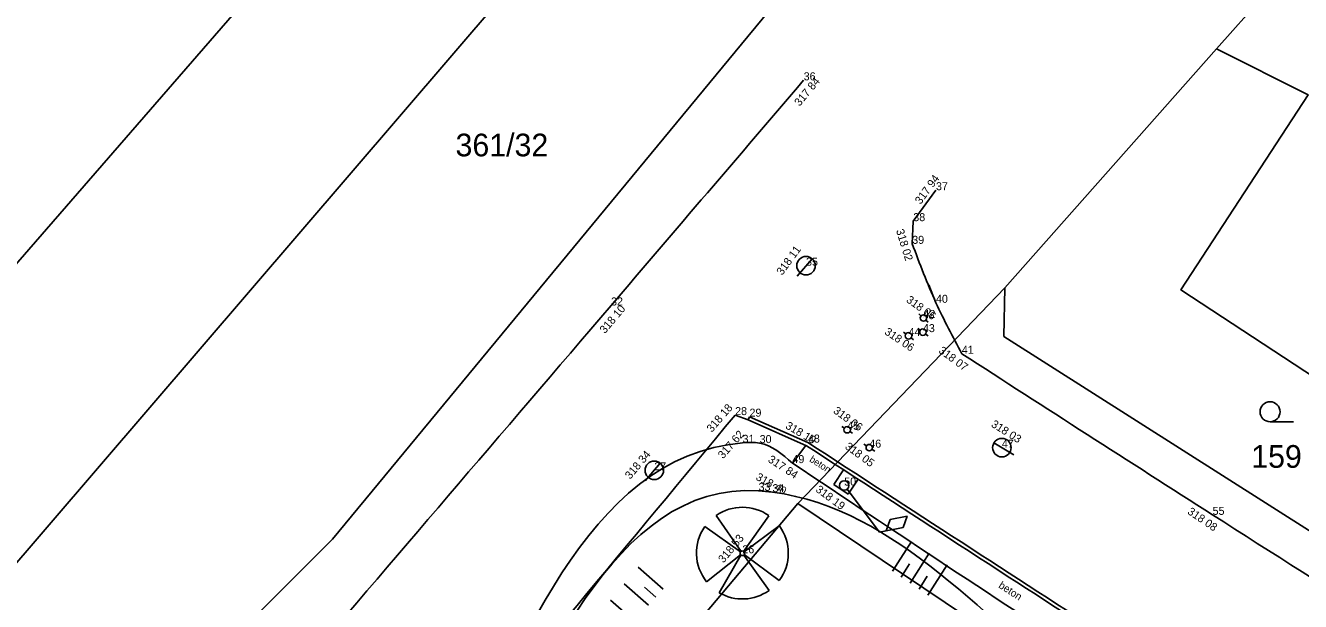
# Model space of a CAD drawing. Extents: x -742884 to -742543, y -1054677 to -1054433.
# Drawn here: x -742753.9 to -742706.11, y -1054488.13 to -1054466.53 of the extents above; entities that cross this region are included whole.
import ezdxf

# ---------------------------------------------------------------- set-up
doc = ezdxf.new("R2010")
doc.units = 0
for name, color, linetype in [('Vrstva 1', 7, 'Continuous'), ('Vrstva 10', 7, 'Continuous'), ('Vrstva 11', 7, 'Continuous'), ('Vrstva 12', 7, 'Continuous'), ('Vrstva 13', 7, 'Continuous'), ('Vrstva 15', 7, 'Continuous'), ('Vrstva 2', 7, 'Continuous'), ('Vrstva 3', 7, 'Continuous'), ('Vrstva 4', 7, 'Continuous'), ('Vrstva 50', 7, 'Continuous'), ('Vrstva 7', 7, 'Continuous'), ('Vrstva 8', 7, 'Continuous'), ('Vrstva 9', 7, 'Continuous')]:
    doc.layers.add(name, color=color, linetype=linetype)

# ---------------------------------------------------------------- blocks, each defined once
blk = doc.blocks.new('Z15')
at = {"layer": 'Vrstva 2'}
for p, q in [((-10, 2), (-8, 6)), ((-10, -2), (-10, 2)), ((-8, 6), (-6, 8)), ((-6, 8), (-2, 10)), ((-2, 10), (2, 10)), ((2, 10), (6, 8)), ((6, 8), (8, 6)), ((8, 6), (10, 2)), ((10, 2), (10, -2)), ((-8, -6), (-10, -2)), ((-6, -8), (-8, -6)), ((-2, -10), (-6, -8)), ((2, -10), (-2, -10)), ((6, -8), (2, -10)), ((8, -6), (6, -8)), ((10, -2), (8, -6))]:
    blk.add_line(p, q, dxfattribs=at)

msp = doc.modelspace()

# ---------------------------------------------------------------- linework, layer by layer
at = {"layer": 'Vrstva 1'}
for p, q in [((-742724.73, -1054468.59), (-742724.73, -1054468.59)), ((-742719.77, -1054472.71), (-742719.77, -1054472.71)), ((-742720.62, -1054473.87), (-742720.62, -1054473.87)), ((-742720.66, -1054474.72), (-742720.66, -1054474.72)), ((-742724.64, -1054475.54), (-742724.64, -1054475.54)), ((-742731.95, -1054477.03), (-742731.95, -1054477.03)), ((-742719.77, -1054476.93), (-742719.77, -1054476.93)), ((-742720.24, -1054477.5), (-742720.24, -1054477.5)), ((-742720.8, -1054478.17), (-742720.8, -1054478.17)), ((-742720.26, -1054478.03), (-742720.26, -1054478.03)), ((-742718.8, -1054478.84), (-742718.8, -1054478.84)), ((-742727.3, -1054481.14), (-742727.3, -1054481.14)), ((-742726.76, -1054481.2), (-742726.76, -1054481.2)), ((-742723.1, -1054481.69), (-742723.1, -1054481.69)), ((-742727.02, -1054482.18), (-742727.02, -1054482.18)), ((-742726.38, -1054482.19), (-742726.38, -1054482.19)), ((-742724.57, -1054482.17), (-742724.57, -1054482.17)), ((-742722.27, -1054482.36), (-742722.27, -1054482.36)), ((-742717.3, -1054482.36), (-742717.3, -1054482.36)), ((-742730.33, -1054483.21), (-742730.33, -1054483.21)), ((-742725.15, -1054482.94), (-742725.15, -1054482.94)), ((-742726.42, -1054483.98), (-742726.42, -1054483.98)), ((-742725.9, -1054484.03), (-742725.9, -1054484.03)), ((-742723.21, -1054483.78), (-742723.21, -1054483.78)), ((-742709.4, -1054484.88), (-742709.4, -1054484.88)), ((-742727.03, -1054486.32), (-742727.03, -1054486.32))]:
    msp.add_line(p, q, dxfattribs=at)
at = {"layer": 'Vrstva 10'}
for p, q in [((-742727.07, -1054486.251), (-742728.008, -1054484.9)), ((-742726.981, -1054486.251), (-742726.03, -1054484.913)), ((-742727.095, -1054486.261), (-742728.434, -1054485.319)), ((-742726.966, -1054486.271), (-742725.644, -1054485.293)), ((-742727.1, -1054486.379), (-742728.368, -1054487.397)), ((-742727.082, -1054486.395), (-742727.897, -1054487.803)), ((-742726.972, -1054486.39), (-742726.028, -1054487.718)), ((-742726.958, -1054486.37), (-742725.644, -1054487.339))]:
    msp.add_line(p, q, dxfattribs=at)
for centre, radius, start, end in [((-742727.026, -1054486.314), 1.72, 54.7465, 124.8105), ((-742727.028, -1054486.31), 1.721, 144.8767, 218.9336), ((-742727.026, -1054486.314), 1.72, 323.4756, 36.2971), ((-742727.026, -1054486.314), 1.72, 239.6151, 305.4552)]:
    msp.add_arc(centre, radius, start, end, dxfattribs=at)
at = {"layer": 'Vrstva 11'}
for p, q in [((-742720.691, -1054485.874), (-742721.401, -1054486.992)), ((-742720.737, -1054487.439), (-742720.025, -1054486.313)), ((-742729.998, -1054487.666), (-742730.939, -1054486.844)), ((-742720.763, -1054486.722), (-742721.073, -1054487.213)), ((-742720.069, -1054487.89), (-742719.349, -1054486.758)), ((-742730.544, -1054488.26), (-742731.459, -1054487.465)), ((-742720.403, -1054487.664), (-742720.095, -1054487.179)), ((-742730.272, -1054487.963), (-742730.698, -1054487.591)), ((-742731.972, -1054488.075), (-742731.082, -1054488.852))]:
    msp.add_line(p, q, dxfattribs=at)
for points in [[(-742777.63, -1054542.12), (-742764.61, -1054526.83), (-742751.7, -1054511.56), (-742738.47, -1054495.82), (-742727.02, -1054482.18), (-742726.38, -1054482.19), (-742725.15, -1054482.94)], [(-742776.7, -1054542.68), (-742764.01, -1054527.79), (-742751.11, -1054512.75), (-742737.61, -1054496.47), (-742726.42, -1054483.98), (-742725.9, -1054484.03), (-742714, -1054491.86), (-742704.819, -1054497.481), (-742700.94, -1054500.269), (-742696.44, -1054503.39), (-742688.83, -1054509.5), (-742682.54, -1054514.17), (-742675.15, -1054519.77), (-742673.01, -1054522.11), (-742671.05, -1054524.7)]]:
    msp.add_spline(points, degree=3, dxfattribs=at)
at = {"layer": 'Vrstva 12'}
for p, q in [((-742723.234, -1054483.19), (-742723.601, -1054483.741)), ((-742723.601, -1054483.741), (-742723.059, -1054484.1)), ((-742722.688, -1054483.544), (-742723.059, -1054484.1))]:
    msp.add_line(p, q, dxfattribs=at)
for points in [[(-742723.103, -1054483.923), (-742721.882, -1054485.535)], [(-742721.633, -1054485.482), (-742721.483, -1054485.059)], [(-742721.483, -1054485.059), (-742720.849, -1054484.926)], [(-742721, -1054485.351), (-742720.849, -1054484.926)], [(-742721.882, -1054485.535), (-742721, -1054485.351)]]:
    msp.add_lwpolyline(points, dxfattribs=at)
msp.add_circle((-742723.212, -1054483.779), 0.18, dxfattribs=at)
at = {"layer": 'Vrstva 13'}
msp.add_line((-742724.65, -1054482.277), (-742725.15, -1054482.94), dxfattribs=at)
msp.add_spline([(-742725.15, -1054482.94), (-742713.48, -1054490.62), (-742699.44, -1054499.41), (-742696.97, -1054500.991)], degree=3, dxfattribs=at)
at = {"layer": 'Vrstva 4'}
for p, q in [((-742719.77, -1054472.71), (-742720.62, -1054473.87)), ((-742720.62, -1054473.87), (-742720.66, -1054474.72)), ((-742720.039, -1054476.262), (-742719.77, -1054476.93)), ((-742727.3, -1054481.14), (-742726.813, -1054481.319)), ((-742726.813, -1054481.319), (-742726.76, -1054481.2)), ((-742726.813, -1054481.319), (-742724.623, -1054482.289)), ((-742724.57, -1054482.17), (-742726.76, -1054481.2))]:
    msp.add_line(p, q, dxfattribs=at)
for points in [[(-742783.23, -1054536.93), (-742770.7, -1054522.44), (-742757.28, -1054506.67), (-742744.15, -1054491.3), (-742731.95, -1054477.03), (-742724.73, -1054468.59)], [(-742720.66, -1054474.72), (-742719.77, -1054476.93), (-742718.8, -1054478.84)], [(-742718.8, -1054478.84), (-742709.4, -1054484.88), (-742695.99, -1054493.43), (-742680.4, -1054503.55), (-742661.01, -1054516), (-742635.78, -1054532.31)], [(-742778.49, -1054541.37), (-742765.63, -1054526.43), (-742752.39, -1054510.77), (-742739.19, -1054495.37), (-742727.3, -1054481.14)], [(-742668.427, -1054518.574), (-742683.74, -1054508.68), (-742696.59, -1054500.4), (-742699.13, -1054498.77), (-742713.15, -1054489.73), (-742724.623, -1054482.289)], [(-742668.31, -1054518.5), (-742683.67, -1054508.57), (-742699.06, -1054498.66), (-742713.08, -1054489.62), (-742724.57, -1054482.17)]]:
    msp.add_spline(points, degree=3, dxfattribs=at)
at = {"layer": 'Vrstva 50'}
for p, q in [((-742780.33, -1054517.08), (-742715.033, -1054440.982)), ((-742700.42, -1054457.44), (-742709.25, -1054467.41)), ((-742709.25, -1054467.41), (-742717.19, -1054476.37)), ((-742717.19, -1054476.37), (-742724.95, -1054484.46)), ((-742707.246, -1054481.39), (-742706.372, -1054481.39))]:
    msp.add_line(p, q, dxfattribs=at)
for points in [[(-742726.76, -1054443.83), (-742775.58, -1054500.01), (-742785.587, -1054491.163)], [(-742771.57, -1054517.32), (-742758.54, -1054501.91), (-742742.39, -1054485.79), (-742708.76, -1054445.064)], [(-742709.25, -1054467.41), (-742705.82, -1054469.13), (-742710.59, -1054476.45), (-742703.26, -1054481.25), (-742695.11, -1054486.47), (-742694.43, -1054486.9)], [(-742717.19, -1054476.37), (-742717.22, -1054478.19), (-742697.33, -1054490.84)], [(-742724.95, -1054484.46), (-742747.39, -1054511.11), (-742766.3, -1054533.47), (-742786.45, -1054556.28), (-742796.57, -1054568.72)], [(-742724.95, -1054484.46), (-742672.19, -1054519.91), (-742671.42, -1054521.73), (-742671.38, -1054524.18), (-742670.45, -1054526.06)]]:
    msp.add_lwpolyline(points, dxfattribs=at)
msp.add_circle((-742707.246, -1054481.015), 0.375, dxfattribs=at)
at = {"layer": 'Vrstva 7'}
for p, q in [((-742724.976, -1054475.931), (-742724.413, -1054475.276)), ((-742716.857, -1054482.624), (-742717.599, -1054482.182)), ((-742730.666, -1054483.601), (-742730.103, -1054482.946))]:
    msp.add_line(p, q, dxfattribs=at)
for centre in [(-742724.64, -1054475.54), (-742717.3, -1054482.36), (-742730.33, -1054483.21)]:
    msp.add_circle(centre, 0.347, dxfattribs=at)
at = {"layer": 'Vrstva 8'}
for p, q in [((-742720.332, -1054477.421), (-742720.418, -1054477.344)), ((-742720.359, -1054477.961), (-742720.453, -1054477.894)), ((-742720.06, -1054477.659), (-742720.149, -1054477.581)), ((-742720.898, -1054478.098), (-742720.99, -1054478.029)), ((-742720.608, -1054478.314), (-742720.703, -1054478.243)), ((-742720.064, -1054478.169), (-742720.161, -1054478.101))]:
    msp.add_line(p, q, dxfattribs=at)
for centre in [(-742720.24, -1054477.5), (-742720.26, -1054478.03), (-742720.8, -1054478.17)]:
    msp.add_circle(centre, 0.121, dxfattribs=at)
at = {"layer": 'Vrstva 9'}
for p, q in [((-742723.202, -1054481.625), (-742723.299, -1054481.562)), ((-742722.898, -1054481.819), (-742722.998, -1054481.756)), ((-742722.372, -1054482.295), (-742722.469, -1054482.232)), ((-742722.068, -1054482.489), (-742722.168, -1054482.426))]:
    msp.add_line(p, q, dxfattribs=at)
for centre in [(-742723.1, -1054481.69), (-742722.27, -1054482.36)]:
    msp.add_circle(centre, 0.121, dxfattribs=at)

# ---------------------------------------------------------------- block references
at = {"layer": 'Vrstva 10', "xscale": 0.008601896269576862, "yscale": 0.008601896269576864, "rotation": -30.671756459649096}
msp.add_blockref('Z15', (-742727.03, -1054486.32), dxfattribs=at)

# ---------------------------------------------------------------- texts
at = {"layer": 'Vrstva 15'}
for height, p in [(0.256, (-742724.535, -1054482.86)), (0.2816, (-742717.45, -1054487.59))]:
    msp.add_text('beton', height=height, rotation=327.2766, dxfattribs=at).set_placement(p)
at = {"layer": 'Vrstva 2'}
for s, p in [('36', (-742724.73, -1054468.59)), ('37', (-742719.77, -1054472.71)), ('38', (-742720.62, -1054473.87)), ('39', (-742720.66, -1054474.72)), ('35', (-742724.64, -1054475.54)), ('32', (-742731.95, -1054477.03)), ('40', (-742719.77, -1054476.93)), ('42', (-742720.24, -1054477.5)), ('44', (-742720.8, -1054478.17)), ('43', (-742720.26, -1054478.03)), ('41', (-742718.8, -1054478.84)), ('28', (-742727.3, -1054481.14)), ('29', (-742726.76, -1054481.2)), ('45', (-742723.1, -1054481.69)), ('31', (-742727.02, -1054482.18)), ('30', (-742726.38, -1054482.19)), ('48', (-742724.57, -1054482.17)), ('46', (-742722.27, -1054482.36)), ('47', (-742717.3, -1054482.36)), ('49', (-742725.15, -1054482.94)), ('27', (-742730.33, -1054483.21)), ('33', (-742726.42, -1054483.98)), ('34', (-742725.9, -1054484.03)), ('50', (-742723.21, -1054483.78)), ('55', (-742709.4, -1054484.88)), ('26', (-742727.03, -1054486.32))]:
    msp.add_text(s, height=0.3, dxfattribs=at).set_placement(p)
at = {"layer": 'Vrstva 3'}
for s, rotation, p in [('317 84 ', 50.4224, (-742724.879, -1054469.581)), ('317 94 ', 53.9863, (-742720.344, -1054473.262)), ('318 02 ', 287.0693, (-742721.271, -1054474.217)), ('318 11 ', 53.7931, (-742725.536, -1054475.92)), ('318 10 ', 49.936, (-742732.179, -1054478.105)), ('318 06 ', 324.5868, (-742720.909, -1054476.88)), ('318 06 ', 325.8809, (-742721.725, -1054478.084)), ('318 07 ', 323.5664, (-742719.696, -1054478.778)), ('318 18 ', 49.2364, (-742728.172, -1054481.809)), ('318 06 ', 323.7555, (-742723.646, -1054481.034)), ('318 03 ', 327.9326, (-742717.727, -1054481.554)), ('317 62 ', 48.8141, (-742727.752, -1054482.8)), ('318 10 ', 329.4578, (-742725.438, -1054481.618)), ('318 05 ', 323.4816, (-742723.206, -1054482.374)), ('318 34 ', 49.8991, (-742731.233, -1054483.567)), ('317 84 ', 326.8368, (-742726.093, -1054482.873)), ('318 40 ', 330.5728, (-742726.55, -1054483.545)), ('318 19 ', 323.4871, (-742724.305, -1054483.986)), ('318 08 ', 325.7772, (-742710.367, -1054484.822)), ('318 53 ', 50.1232, (-742727.735, -1054486.706))]:
    msp.add_text(s, height=0.3, rotation=rotation, dxfattribs=at).set_placement(p)
at = {"layer": 'Vrstva 50'}
for s, p in [('361/32', (-742737.78, -1054471.44)), ('159', (-742707.952, -1054483.115))]:
    msp.add_text(s, height=0.85, dxfattribs=at).set_placement(p)

doc.saveas('drawing.dxf')
